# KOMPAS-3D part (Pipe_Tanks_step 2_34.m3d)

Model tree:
1. X Axis
2. Y Axis
3. Z Axis  (labels: Pipe Dn 50)
     Òîëùèíà ñòåíêè 1 = 1

Referenced files in C:\Documents and Settings\kashirsky\Мои документы\Camtasia Studio\Pipelines3D\Tanks\: Tanks_step 2.a3d
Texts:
  Pipe Dn 50
  Steel ASTM A295
  Three Point Plane
  Plane at Angle
  Line and Point Plane
  Axis through Two Vertices
  Axis of Feature
  Axis of Conical Surface
  Axis through Edge
  Trim by Surface
  Trim by Sketch
  Feature with No History
  Intersection Axis of Two Planes
  Two Line Plane
  Line and Face Plane
  Bend by line
  Hole in sheet body
  Cut in sheet body
  Point in CM
  Linear Dimension from Line to Point
  Surface Finish Symbol
  Geometric Tolerance Symbol
  Leader #1
  Leader #2
  Leader #3
  Shape Deviations and Datum
  Node point number
  Mark of coordination axis
  Node point designation
  Mark/Reference designation with leader
  Mark/reference designation on line
  Mark/Reference designation without leader
  Plane of section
